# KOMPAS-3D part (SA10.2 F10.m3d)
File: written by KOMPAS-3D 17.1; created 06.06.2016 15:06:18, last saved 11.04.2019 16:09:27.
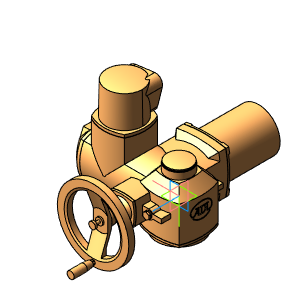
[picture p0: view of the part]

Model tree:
1. Операция без истории:4  (labels: Сталь 20  ГОСТ 1050-88)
